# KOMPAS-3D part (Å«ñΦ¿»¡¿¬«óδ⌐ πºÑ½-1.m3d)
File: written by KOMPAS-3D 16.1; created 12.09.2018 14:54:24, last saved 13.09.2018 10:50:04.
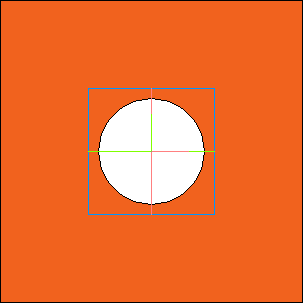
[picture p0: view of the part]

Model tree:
1. Эскиз:2
2. Операция выдавливания:1  (labels: Полипропилен  ГОСТ 26996-86)
     Расстояние 1 = 20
